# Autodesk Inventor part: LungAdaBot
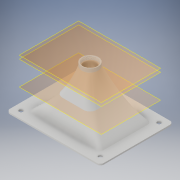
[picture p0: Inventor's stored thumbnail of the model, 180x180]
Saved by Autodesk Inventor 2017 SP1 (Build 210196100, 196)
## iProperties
Part Number: LungAdaBot
Material: Generisch
Document SubType Name: Modeling
Designer: haesner
Density: 1 g/cm^3
Appearance: Vorgabe
Part Number: LungAdaBot_3D-Druck
Author: haesner
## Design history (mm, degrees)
sketch "Skizze3"
  geometry: L1 (-48, 38)-(48, 38); L2 (53, 33)-(53, -33); L3 (48, -38)-(-48, -38); L4 (-53, -33)-(-53, 33); L5 (-75.65, 0)-(75.65, 0) reference; L6 (0, -54.65)-(0, 54.65) reference; A1 r 5 centre (48, 33) between (53, 33) and (48, 38); A2 r 5 centre (-48, 33) between (-48, 38) and (-53, 33); A3 r 5 centre (-48, -33) between (-53, -33) and (-48, -38); A4 r 5 centre (48, -33) between (48, -38) and (53, -33); 4 further points
  constraints: 8 end point, 8 point on circle, 8 tangent, 6 point on line, 4 centre point, 3 equal radius, 2 parallel, 1 horizontal, 1 perpendicular, 2 other
  dimensions: "d29" = 106 distance of point (-53, 38) point (53, 38); "d30" = 76 distance of point (-53, -38) point (-53, 38); "d31" = 5 radius of A1 (derived)
workplane "Arbeitsebene2"
sketch "Skizze4"
  geometry: L1 (15, 25)-(-15, 25); L2 (-25, 15)-(-25, -15); L3 (-15, -25)-(15, -25); L4 (25, -15)-(25, 15); L5 (0, -54.65)-(0, 54.65) reference; L6 (-75.65, 0)-(75.65, 0) reference; A1 r 10 centre (-15, 15) between (-15, 25) and (-25, 15); A2 r 10 centre (15, 15) between (25, 15) and (15, 25); A3 r 10 centre (15, -15) between (15, -25) and (25, -15); A4 r 10 centre (-15, -15) between (-25, -15) and (-15, -25); 3 further points
  constraints: 8 end point, 8 point on circle, 8 tangent, 4 centre point, 4 point on line, 3 equal radius, 2 parallel, 2 perpendicular, 1 horizontal, 2 other
  dimensions: "d33" = 50 distance of point (25, 25) point (-25, 25); "d34" = 10 radius of A1
workplane "Arbeitsebene3"
sketch "Skizze5"
  geometry: C1 r 12 at (0, 0); 1 further point
  constraints: 1 centre point, 1 coincident
  dimensions: "d36" = 24 diameter of C1
feature "Erhebung1" sketch "Skizze5" dims "d37" = 0, "d38" = 90 deg, "d39" = 0, "d40" = 90 deg, "d41" = 0, "d42" = 90 deg
feature "Wandung1" dims "d43" = 3
sketch "Skizze11"
  geometry: 3 further points
  constraints: 2 other
extrude "Extrusion2" join sketch "Skizze11" distance "d50" = 1; taper "d51" = 0 deg
sketch "Skizze13"
  geometry: L1 (50, 30)-(50, -30) reference; L2 (45, -35)-(-45, -35) reference; L3 (-50, -30)-(-50, 30) reference; L4 (-45, 35)-(45, 35) reference; L5 (-63, 53)-(63, 53); L6 (68, 48)-(68, -48); L7 (63, -53)-(-63, -53); L8 (-68, -48)-(-68, 48); L9 (0, -75.65)-(0, 75.65) reference; L10 (96.65, 0)-(-96.65, 0) reference; A1 r 5 centre (45, 30) between (50, 30) and (45, 35) reference; A2 r 5 centre (45, -30) between (45, -35) and (50, -30) reference; A3 r 5 centre (-45, -30) between (-50, -30) and (-45, -35) reference; A4 r 5 centre (-45, 30) between (-45, 35) and (-50, 30) reference; A5 r 5 centre (-63, 48) between (-63, 53) and (-68, 48); A6 r 5 centre (63, 48) between (68, 48) and (63, 53); A7 r 5 centre (63, -48) between (63, -53) and (68, -48); A8 r 5 centre (-63, -48) between (-68, -48) and (-63, -53); 4 further points
  constraints: 8 end point, 8 point on circle, 8 tangent, 6 point on line, 4 centre point, 3 equal radius, 2 parallel, 1 horizontal, 1 perpendicular, 2 other
  dimensions: "d57" = 136 distance of point (-68, 53) point (68, 53); "d58" = 106 distance of point (-68, -53) point (-68, 53); "d59" = 5 radius of A5 (derived)
extrude "Extrusion5" join sketch "Skizze13" distance "d62" = 2; taper "d63" = 0 deg
sketch "Skizze15"
  geometry: L1 (57.5, 42.5)-(-57.5, 42.5); L2 (-57.5, 42.5)-(-57.5, -42.5); L3 (-57.5, -42.5)-(57.5, -42.5); L4 (57.5, -42.5)-(57.5, 42.5); L5 (-95.2, 0)-(95.2, 0) reference; L6 (0, 74.2)-(0, -74.2) reference; 1 further point
  constraints: 8 end point, 2 parallel, 1 horizontal, 1 perpendicular, 2 other
  dimensions: "d64" = 85 distance of L3.end L1.start; "d65" = 115 distance of L2.end L3.end
hole "Bohrung1" sketch "Skizze15" at (57.5, 42.5), (-57.5, 42.5), (-57.5, -42.5), (57.5, -42.5) diameter "d66" = 5.5; stored, may be unused: countersink angle "d70" = 90 deg, drill point angle "d72" = 118 deg; dims "d67" = 6, "d68" = 10.4, "d69" = 2, "d71" = 8
sketch "Skizze16"
  geometry: 4 further points
  constraints: 1 horizontal alignment, 1 other
extrude "Extrusion6" join sketch "Skizze16" distance "d73" = 5; taper "d74" = 0 deg
sketch "Skizze17"
  geometry: C1 r 9 at (0, 0); 1 further point
  constraints: 1 centre point, 1 coincident
  dimensions: "d75" = 18 diameter of C1
extrude "Extrusion7" cut sketch "Skizze17" distance "d76" = 15; taper "d77" = 0 deg
sketch "Skizze18"
  geometry: C1 r 11 at (0, 0); 1 further point
  constraints: 1 centre point, 1 coincident
  dimensions: "d78" = 22 diameter of C1
extrude "Extrusion8" cut sketch "Skizze18" distance "d79" = 5; taper "d80" = 0 deg
sketch "Skizze19"
  geometry: L1 (-11.5, 65)-(-11.5, 64); L2 (-11.5, 64)-(-11, 64); L3 (-11, 64)-(-10.414, 64.419); L4 (-10.414, 64.581)-(-11, 65); L5 (-11, 65)-(-11.5, 65); L6 (-95.2, 65)-(95.2, 65) reference; L7 (-11, 70)-(-11, 65) reference; A1 r 0.1 centre (-10.472, 64.5) between (-10.414, 64.419) and (-10.414, 64.581); 2 further points
  constraints: 10 end point, 3 point on line, 2 equal length, 2 point on circle, 2 tangent, 1 centre point, 1 collinear, 1 parallel, 1 perpendicular, 1 vertical
  dimensions: "d81" = 0.7 horizontal distance of L4.end point (-10.3, 64.5); "d82" = 1 distance of L1.start L1.end; "d83" = 0.5 distance of L1.end L2.end; "d84" = 0.1 radius of A1
feature "Spirale1" sketch "Skizze19" pitch "d85" = 1; turns "d87" = 8; dims "d86" = 10, "d88" = 0, angle "d89" = 90 deg, angle "d90" = 90 deg, "d91" = 0, "d92" = 0
workplane "Arbeitsebene5"
feature "Trennen2"
node "Volumenkörper2"
node "Projizierte Kontur3"
other parameters: "d35" = 35, "d93" = 5
